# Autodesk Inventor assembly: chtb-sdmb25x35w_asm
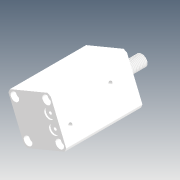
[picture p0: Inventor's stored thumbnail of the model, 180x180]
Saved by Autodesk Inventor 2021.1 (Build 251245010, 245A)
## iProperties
Company: Microsoft
Created: 2018-05
Part Number: chtb-sdmb25x35w_asm
Description: STEP AP214
Document SubType Name: Assembly
Designer: user
Title: chtb-sdmb25x35w_asm.STEP
Author: Windows
Revision Number: ÈÎºÎ
Sending System: SolidWorks 2015
Preprocessor: SwSTEP 2.0
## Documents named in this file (4)
- D:\Vault_2016\Projekty\Clamptek\Hydraulic\CHTB\CHTB-25\Inventor\chtb-sdmb25x35w\chtb-sdmb25x35w_asm.iam
- D:\Vault_2016\Projekty\Clamptek\Hydraulic\CHTB\CHTB-25\Inventor\chtb-sdmb25x35w\CHTB-25QG.ipt
- D:\Vault_2016\Projekty\Clamptek\Hydraulic\CHTB\CHTB-25\Inventor\chtb-sdmb25x35w\CHTB-SDMB25X35NBT.ipt
- D:\Vault_2016\Projekty\Clamptek\Hydraulic\CHTB\CHTB-25\Inventor\chtb-sdmb25x35w\CHTB-SDMB25X35WHSG.ipt
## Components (3 placed, 3 different names)
1. CHTB-25QG_1
2. CHTB-SDMB25X35NBT_2
3. CHTB-SDMB25X35WHSG_3
